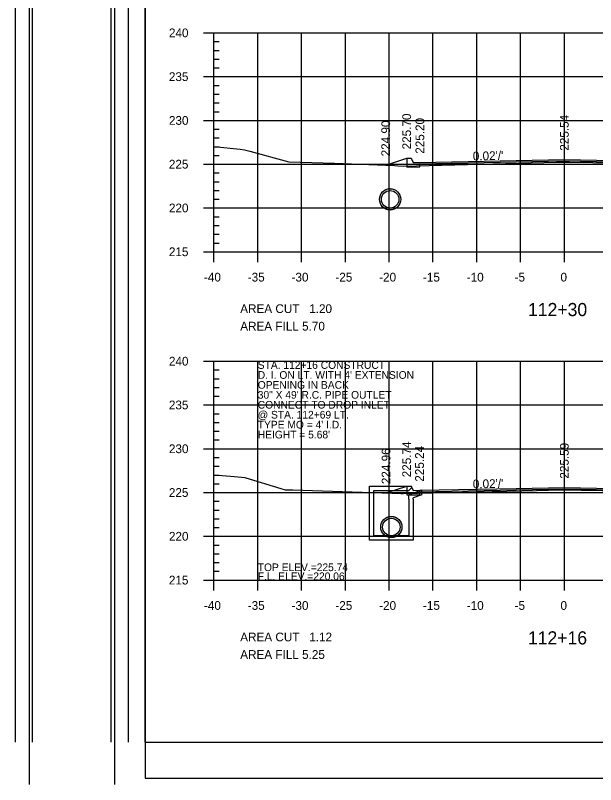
# Model space of a CAD drawing. Extents: x 1367903 to 1373764, y 376865 to 382130.
# Drawn here: x 1373046.4 to 1373178.8, y 377279.1 to 377454.8 of the extents above; entities that cross this region are included whole.
import ezdxf

# ---------------------------------------------------------------- set-up
doc = ezdxf.new("R2010")
doc.units = 0
for name, color, linetype in [('R_Axis', 7, 'Continuous'), ('R_Axis Annot', 7, 'Continuous'), ('R_Border', 7, 'Continuous'), ('R_Border PE', 7, 'Continuous'), ('R_Draft', 7, 'Continuous'), ('R_Exist Surface', 7, 'Continuous'), ('R_Fin Surface', 7, 'Continuous'), ('R_Fin Surface Annot', 7, 'Continuous'), ('R_Grid', 7, 'Continuous'), ('R_Water', 7, 'Continuous'), ('R_Water Annot', 7, 'Continuous')]:
    doc.layers.add(name, color=color, linetype=linetype)

msp = doc.modelspace()

# ---------------------------------------------------------------- linework, layer by layer
for p, q in [((1373127.19, 377347.32), (1373136.69, 377347.32)), ((1373127.19, 377344.32), (1373127.19, 377347.32)), ((1373136.85, 377346.98), (1373136.69, 377347.32)), ((1373128.19, 377344.32), (1373128.19, 377346.32)), ((1373128.19, 377346.32), (1373136.19, 377346.32)), ((1373136.85, 377346.98), (1373136.19, 377346.32)), ((1373139.19, 377346.36), (1373136.19, 377345.32)), ((1373136.19, 377344.32), (1373136.19, 377345.32)), ((1373139.19, 377345.3), (1373137.19, 377344.6)), ((1373137.19, 377344.32), (1373137.19, 377344.6))]:
    msp.add_line(p, q)
for points in [[(1373135.69, 377422.23), (1373135.69, 377421.56), (1373135.69, 377421.56), (1373135.69, 377420.2), (1373138.69, 377420.26), (1373138.69, 377420.92), (1373171.69, 377421.58), (1373204.69, 377420.92), (1373204.69, 377420.26), (1373207.69, 377420.2), (1373207.69, 377421.64), (1373221.69, 377421.92), (1373221.69, 377422.51)], [(1373135.69, 377347.32), (1373135.69, 377346.65), (1373135.69, 377346.65), (1373135.69, 377345.29), (1373138.69, 377345.35), (1373138.69, 377346.01), (1373171.69, 377346.67), (1373204.69, 377346.01), (1373204.69, 377345.35), (1373207.69, 377345.29), (1373207.69, 377346.73), (1373221.69, 377347.01), (1373221.69, 377347.6)], [(1373139.19, 377345.3), (1373139.19, 377346.36)]]:
    msp.add_lwpolyline(points)
at = {"layer": 'R_Axis'}
for p, q in [((1373089.29, 377450.84), (1373094.09, 377450.84)), ((1373091.69, 377400.84), (1373091.69, 377450.84)), ((1373091.69, 377448.84), (1373092.89, 377448.84)), ((1373091.69, 377446.84), (1373092.89, 377446.84)), ((1373091.69, 377444.84), (1373092.89, 377444.84)), ((1373091.69, 377442.84), (1373092.89, 377442.84)), ((1373089.29, 377440.84), (1373094.09, 377440.84)), ((1373091.69, 377438.84), (1373092.89, 377438.84)), ((1373091.69, 377436.84), (1373092.89, 377436.84)), ((1373091.69, 377434.84), (1373092.89, 377434.84)), ((1373091.69, 377432.84), (1373092.89, 377432.84)), ((1373089.29, 377430.84), (1373094.09, 377430.84)), ((1373091.69, 377428.84), (1373092.89, 377428.84)), ((1373091.69, 377426.84), (1373092.89, 377426.84)), ((1373091.69, 377424.84), (1373092.89, 377424.84)), ((1373091.69, 377422.84), (1373092.89, 377422.84)), ((1373089.29, 377420.84), (1373094.09, 377420.84)), ((1373091.69, 377418.84), (1373092.89, 377418.84)), ((1373091.69, 377416.84), (1373092.89, 377416.84)), ((1373091.69, 377414.84), (1373092.89, 377414.84)), ((1373091.69, 377412.84), (1373092.89, 377412.84)), ((1373089.29, 377410.84), (1373094.09, 377410.84)), ((1373091.69, 377408.84), (1373092.89, 377408.84)), ((1373091.69, 377406.84), (1373092.89, 377406.84)), ((1373091.69, 377404.84), (1373092.89, 377404.84)), ((1373091.69, 377398.44), (1373091.69, 377403.24)), ((1373091.69, 377402.84), (1373092.89, 377402.84)), ((1373101.69, 377398.44), (1373101.69, 377403.24)), ((1373111.69, 377398.44), (1373111.69, 377403.24)), ((1373121.69, 377398.44), (1373121.69, 377403.24)), ((1373131.69, 377398.44), (1373131.69, 377403.24)), ((1373141.69, 377398.44), (1373141.69, 377403.24)), ((1373151.69, 377398.44), (1373151.69, 377403.24)), ((1373161.69, 377398.44), (1373161.69, 377403.24)), ((1373171.69, 377398.44), (1373171.69, 377403.24)), ((1373089.29, 377400.84), (1373094.09, 377400.84)), ((1373091.69, 377400.84), (1373251.69, 377400.84)), ((1373089.29, 377375.84), (1373094.09, 377375.84)), ((1373091.69, 377325.84), (1373091.69, 377375.84)), ((1373091.69, 377373.84), (1373092.89, 377373.84)), ((1373091.69, 377371.84), (1373092.89, 377371.84)), ((1373091.69, 377369.84), (1373092.89, 377369.84)), ((1373091.69, 377367.84), (1373092.89, 377367.84)), ((1373089.29, 377365.84), (1373094.09, 377365.84)), ((1373091.69, 377363.84), (1373092.89, 377363.84)), ((1373091.69, 377361.84), (1373092.89, 377361.84)), ((1373091.69, 377359.84), (1373092.89, 377359.84)), ((1373091.69, 377357.84), (1373092.89, 377357.84)), ((1373089.29, 377355.84), (1373094.09, 377355.84)), ((1373091.69, 377353.84), (1373092.89, 377353.84)), ((1373091.69, 377351.84), (1373092.89, 377351.84)), ((1373091.69, 377349.84), (1373092.89, 377349.84)), ((1373091.69, 377347.84), (1373092.89, 377347.84)), ((1373089.29, 377345.84), (1373094.09, 377345.84)), ((1373091.69, 377343.84), (1373092.89, 377343.84)), ((1373091.69, 377341.84), (1373092.89, 377341.84)), ((1373091.69, 377339.84), (1373092.89, 377339.84)), ((1373091.69, 377337.84), (1373092.89, 377337.84)), ((1373089.29, 377335.84), (1373094.09, 377335.84)), ((1373091.69, 377333.84), (1373092.89, 377333.84)), ((1373091.69, 377331.84), (1373092.89, 377331.84)), ((1373091.69, 377329.84), (1373092.89, 377329.84)), ((1373091.69, 377323.44), (1373091.69, 377328.24)), ((1373091.69, 377327.84), (1373092.89, 377327.84)), ((1373101.69, 377323.44), (1373101.69, 377328.24)), ((1373111.69, 377323.44), (1373111.69, 377328.24)), ((1373121.69, 377323.44), (1373121.69, 377328.24)), ((1373131.69, 377323.44), (1373131.69, 377328.24)), ((1373141.69, 377323.44), (1373141.69, 377328.24)), ((1373151.69, 377323.44), (1373151.69, 377328.24)), ((1373161.69, 377323.44), (1373161.69, 377328.24)), ((1373171.69, 377323.44), (1373171.69, 377328.24)), ((1373089.29, 377325.84), (1373094.09, 377325.84)), ((1373091.69, 377325.84), (1373251.69, 377325.84))]:
    msp.add_line(p, q, dxfattribs=at)
at = {"layer": 'R_Border'}
for p, q in [((1373049.47, 377620.35), (1373049.47, 377279.12)), ((1373068.96, 377620.35), (1373068.96, 377279.12)), ((1373075.99, 377611.47), (1373075.99, 377280.59)), ((1373075.99, 377280.59), (1373280.31, 377280.59))]:
    msp.add_line(p, q, dxfattribs=at)
at = {"layer": 'R_Border PE'}
for p, q in [((1373046.36, 377288.8), (1373046.36, 377610.76)), ((1373050.27, 377288.8), (1373050.27, 377610.76)), ((1373068.15, 377610.76), (1373068.15, 377288.8)), ((1373072.07, 377610.76), (1373072.07, 377288.8)), ((1373075.99, 377288.8), (1373075.99, 377603.25)), ((1373075.99, 377288.8), (1373280.31, 377288.8))]:
    msp.add_line(p, q, dxfattribs=at)
at = {"layer": 'R_Exist Surface'}
for points in [[(1373091.69, 377424.85), (1373097.66, 377424.25), (1373098.69, 377424.14), (1373099.88, 377423.83), (1373108.81, 377421.39), (1373119.23, 377421.04), (1373132.94, 377420.56), (1373133.69, 377420.45), (1373135.08, 377420.39), (1373169.93, 377421.29), (1373170.88, 377421.32), (1373172.84, 377421.29), (1373204.74, 377420.88)], [(1373091.69, 377349.92), (1373096.41, 377349.47), (1373098.71, 377349.25), (1373098.98, 377349.16), (1373106.98, 377346.74), (1373107.98, 377346.49), (1373108.83, 377346.44), (1373109.69, 377346.42), (1373132.3, 377345.7), (1373134.33, 377345.63), (1373134.95, 377345.6), (1373165.31, 377346.33), (1373170.9, 377346.46), (1373199.24, 377346.01)]]:
    msp.add_lwpolyline(points, dxfattribs=at)
at = {"layer": 'R_Fin Surface'}
for points in [[(1373130.9, 377420.63), (1373135.69, 377422.23), (1373136.69, 377422.23), (1373137.19, 377421.23), (1373138.69, 377421.26), (1373160.69, 377421.7), (1373171.69, 377421.92), (1373182.69, 377421.7), (1373204.69, 377421.26), (1373206.19, 377421.23), (1373206.69, 377422.23), (1373207.69, 377422.23), (1373211.69, 377422.31), (1373221.69, 377422.51), (1373222.15, 377422.35)], [(1373130.98, 377345.75), (1373135.69, 377347.32), (1373136.69, 377347.32), (1373137.19, 377346.32), (1373138.69, 377346.35), (1373160.69, 377346.79), (1373171.69, 377347.01), (1373182.69, 377346.79), (1373204.69, 377346.35), (1373206.19, 377346.32), (1373206.69, 377347.32), (1373207.69, 377347.32), (1373211.69, 377347.4), (1373221.69, 377347.6), (1373221.95, 377347.51)]]:
    msp.add_lwpolyline(points, dxfattribs=at)
at = {"layer": 'R_Grid'}
for p, q in [((1373091.69, 377450.84), (1373251.69, 377450.84)), ((1373091.69, 377400.84), (1373091.69, 377450.84)), ((1373101.69, 377400.84), (1373101.69, 377450.84)), ((1373111.69, 377400.84), (1373111.69, 377450.84)), ((1373121.69, 377400.84), (1373121.69, 377450.84)), ((1373131.69, 377400.84), (1373131.69, 377450.84)), ((1373141.69, 377400.84), (1373141.69, 377450.84)), ((1373151.69, 377400.84), (1373151.69, 377450.84)), ((1373161.69, 377400.84), (1373161.69, 377450.84)), ((1373171.69, 377400.84), (1373171.69, 377450.84)), ((1373091.69, 377440.84), (1373251.69, 377440.84)), ((1373091.69, 377430.84), (1373251.69, 377430.84)), ((1373091.69, 377420.84), (1373251.69, 377420.84)), ((1373091.69, 377410.84), (1373251.69, 377410.84)), ((1373091.69, 377400.84), (1373251.69, 377400.84)), ((1373091.69, 377375.84), (1373251.69, 377375.84)), ((1373091.69, 377325.84), (1373091.69, 377375.84)), ((1373101.69, 377325.84), (1373101.69, 377375.84)), ((1373111.69, 377325.84), (1373111.69, 377375.84)), ((1373121.69, 377325.84), (1373121.69, 377375.84)), ((1373131.69, 377325.84), (1373131.69, 377375.84)), ((1373141.69, 377325.84), (1373141.69, 377375.84)), ((1373151.69, 377325.84), (1373151.69, 377375.84)), ((1373161.69, 377325.84), (1373161.69, 377375.84)), ((1373171.69, 377325.84), (1373171.69, 377375.84)), ((1373091.69, 377365.84), (1373251.69, 377365.84)), ((1373091.69, 377355.84), (1373251.69, 377355.84)), ((1373091.69, 377345.84), (1373251.69, 377345.84)), ((1373091.69, 377335.84), (1373251.69, 377335.84)), ((1373091.69, 377325.84), (1373251.69, 377325.84))]:
    msp.add_line(p, q, dxfattribs=at)
at = {"layer": 'R_Water'}
for p, q in [((1373131.95, 377415.25), (1373131.87, 377415.2)), ((1373131.95, 377414.83), (1373131.87, 377414.79)), ((1373131.95, 377410.83), (1373131.87, 377410.79)), ((1373131.95, 377410.42), (1373131.87, 377410.37))]:
    msp.add_line(p, q, dxfattribs=at)
for points in [[(1373137.19, 377344.32), (1373137.19, 377334.95), (1373132.19, 377334.95), (1373127.19, 377334.95), (1373127.19, 377344.32)], [(1373136.19, 377344.32), (1373136.19, 377335.95), (1373132.19, 377335.95), (1373128.19, 377335.95), (1373128.19, 377344.32)]]:
    msp.add_lwpolyline(points, dxfattribs=at)
for centre, radius in [((1373131.91, 377412.81), 2.42), ((1373131.91, 377412.81), 2), ((1373132.19, 377337.96), 2.42), ((1373132.19, 377337.95), 2.42), ((1373132.19, 377337.96), 2), ((1373132.19, 377337.95), 2)]:
    msp.add_circle(centre, radius, dxfattribs=at)

# ---------------------------------------------------------------- texts
at = {"layer": 'R_Axis Annot'}
for s, height, p in [('240', 2, (1373081.41, 377449.84)), ('235', 2, (1373081.4, 377439.84)), ('230', 2, (1373081.41, 377429.84)), ('225', 2, (1373081.4, 377419.84)), ('220', 2, (1373081.41, 377409.84)), ('215', 2, (1373081.4, 377399.84)), ('-40', 2, (1373089.41, 377394.04)), ('-35', 2, (1373099.41, 377394.04)), ('-30', 2, (1373109.41, 377394.04)), ('-25', 2, (1373119.41, 377394.04)), ('-20', 2, (1373129.41, 377394.04)), ('-15', 2, (1373139.41, 377394.04)), ('-10', 2, (1373149.41, 377394.04)), ('-5', 2, (1373160.34, 377394.04)), ('0', 2, (1373170.81, 377394.04)), ('AREA CUT   1.20', 2, (1373097.69, 377386.84)), ('112+30', 3, (1373163.4, 377386.14)), ('AREA FILL 5.70', 2, (1373097.69, 377382.84)), ('240', 2, (1373081.41, 377374.84)), ('235', 2, (1373081.4, 377364.84)), ('230', 2, (1373081.41, 377354.84)), ('225', 2, (1373081.4, 377344.84)), ('220', 2, (1373081.41, 377334.84)), ('215', 2, (1373081.4, 377324.84)), ('-40', 2, (1373089.41, 377319.04)), ('-35', 2, (1373099.41, 377319.04)), ('-30', 2, (1373109.41, 377319.04)), ('-25', 2, (1373119.41, 377319.04)), ('-20', 2, (1373129.41, 377319.04)), ('-15', 2, (1373139.41, 377319.04)), ('-10', 2, (1373149.41, 377319.04)), ('-5', 2, (1373160.34, 377319.04)), ('0', 2, (1373170.81, 377319.04)), ('AREA CUT   1.12', 2, (1373097.69, 377311.84)), ('112+16', 3, (1373163.38, 377311.14)), ('AREA FILL 5.25', 2, (1373097.69, 377307.84))]:
    msp.add_text(s, height=height, dxfattribs=at).set_placement(p)
at = {"layer": 'R_Draft'}
for s, p in [('STA. 112+16 CONSTRUCT', (1373101.69, 377374.09)), ("D. I. ON LT. WITH 4' EXTENSION", (1373101.69, 377371.82)), ('OPENING IN BACK', (1373101.69, 377369.55)), ('30" X 49\' R.C. PIPE OUTLET', (1373101.69, 377367.28)), ('CONNECT TO DROP INLET', (1373101.69, 377365.01)), ('@ STA. 112+69 LT.', (1373101.69, 377362.74)), ("TYPE MO = 4' I.D.", (1373101.69, 377360.47)), ("HEIGHT = 5.68'", (1373101.69, 377358.2))]:
    msp.add_text(s, height=1.75, dxfattribs=at).set_placement(p)
at = {"layer": 'R_Fin Surface Annot'}
for s, rotation, p in [('225.70', 90, (1373136.69, 377424.23)), ('225.54', 90, (1373172.69, 377423.92)), ('224.90', 90, (1373131.9, 377422.63)), ('225.20', 90, (1373139.71, 377423.23)), ("0.02'/'", 1.1458, (1373150.81, 377421.7)), ('225.74', 90, (1373136.69, 377349.32)), ('225.24', 90, (1373139.62, 377348.32)), ('225.59', 90, (1373172.69, 377349.01)), ('224.96', 90, (1373131.98, 377347.75)), ("0.02'/'", 1.1458, (1373150.81, 377346.79))]:
    msp.add_text(s, height=2, rotation=rotation, dxfattribs=at).set_placement(p)
at = {"layer": 'R_Water Annot'}
for s, p in [('TOP ELEV.=225.74', (1373101.69, 377327.89)), ('F.L. ELEV.=220.06', (1373101.69, 377325.84))]:
    msp.add_text(s, height=1.75, dxfattribs=at).set_placement(p)

doc.saveas('drawing.dxf')
